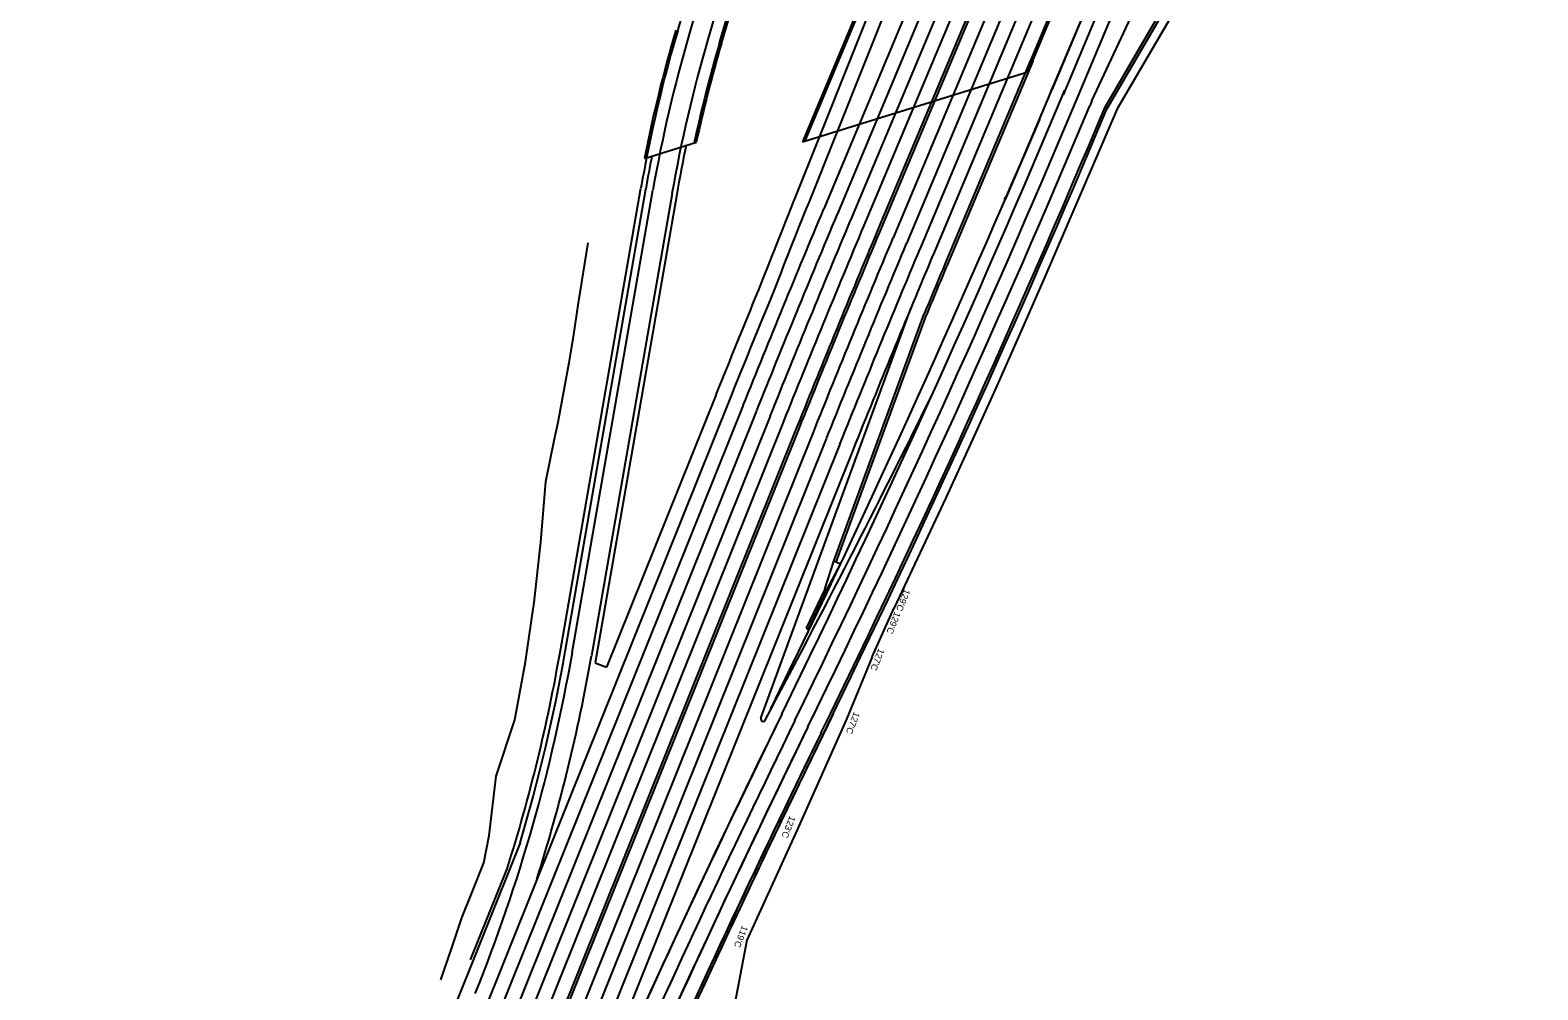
# Model space of a CAD drawing. Extents: x 1942118 to 1978871, y 789467 to 829913.
# Drawn here: x 1967729 to 1968973, y 795860 to 796652 of the extents above; entities that cross this region are included whole.
import ezdxf

# ---------------------------------------------------------------- set-up
doc = ezdxf.new("R2010")
doc.units = 0
for name, color, linetype in [('BR_CONCRETE', 7, 'Continuous'), ('RD_PD_ALT1_TrvlWay', 7, 'Continuous'), ('RD_PD_CstnLmt', 7, 'Continuous'), ('RD_PD_Final_LnLine', 7, 'Continuous'), ('RD_PD_Final_TrvlWay', 7, 'Continuous'), ('RD_PD_GR', 7, 'Continuous'), ('RD_PD_MedBWall', 7, 'Continuous'), ('RD_PD_PaveShd', 7, 'Continuous'), ('RD_PD_TX_CstnLmt', 7, 'Continuous'), ('RD_PD_WallFill', 7, 'Continuous'), ('RD_QTY_Conc4Structures', 7, 'Continuous')]:
    doc.layers.add(name, color=color, linetype=linetype)

msp = doc.modelspace()

# ---------------------------------------------------------------- linework, layer by layer
at = {"layer": 'BR_CONCRETE'}
for p, q in [((1968667.1, 797277.4), (1968366.4, 796560.2)), ((1968668.6, 797276.7), (1968368.4, 796560.9)), ((1968803.3, 797220.3), (1968550.4, 796617.4)), ((1968804.8, 797219.6), (1968552.4, 796618)), ((1968263.5, 796651.9), (1968353.7, 796958.7)), ((1968298.1, 796641.8), (1968388.3, 796948.5)), ((1968299.6, 796641.3), (1968389.8, 796948.1)), ((1968366.4, 796560.2), (1968552.4, 796618)), ((1968236.1, 796546.5), (1968278.9, 796559.8))]:
    msp.add_line(p, q, dxfattribs=at)
for radius, end in [(1177.6, 168.9156), (1176, 168.873), (1140, 167.8912), (1138.4, 167.8451)]:
    msp.add_arc((1969391.7, 796320.1), radius, 163.611, end, dxfattribs=at)
at = {"layer": 'RD_PD_ALT1_TrvlWay'}
for p, q in [((1968735, 797248.9), (1968417.2, 796491)), ((1968759, 797238.8), (1968441.2, 796480.9)), ((1968792.2, 797224.9), (1968474.4, 796467)), ((1968600.4, 797083.1), (1968371.6, 796510.1)), ((1968273.1, 796649.1), (1968363.3, 796955.9)), ((1968288.5, 796644.6), (1968378.7, 796951.3)), ((1968176.5, 796138.5), (1968243, 796520.2)), ((1968258.8, 796517.4), (1968192.3, 796135.8)), ((1968332.2, 796084.4), (1968455.8, 796422.5)), ((1968306.3, 796347.2), (1968147.2, 795951.2)), ((1968350.8, 796329.3), (1967751.3, 794836.6)), ((1968374.9, 796319.6), (1968148.1, 795754.9)), ((1968408.3, 796306.2), (1968052.1, 795419.3))]:
    msp.add_line(p, q, dxfattribs=at)
for centre, radius, start, end in [((1969391.7, 796320.1), 1166, 163.611, 170.119), ((1969391.7, 796320.1), 1150, 163.611, 170.119), ((1979068.7, 792236.5), 11519.2, 158.2228, 158.6386), ((1978996.5, 792053.9), 11472.2, 157.24601, 158.11901), ((1978996.5, 792053.9), 11446.2, 157.24601, 158.11901), ((1978996.5, 792053.9), 11410.2, 157.24601, 158.11901), ((1978996.5, 792053.9), 11520.2, 157.66169, 158.11901), ((1959776.5, 800641.6), 9697.6, 331.95974, 333.73393), ((1966797.3, 796378.8), 1400, 338.119, 350.119), ((1966797.3, 796378.8), 1416, 342.4266, 350.119), ((1977342.9, 791688), 10012, 153.93129, 158.11901), ((1968334.1, 796083.7), 2, 159.9191, 331.9597), ((1977342.9, 791688), 9988, 153.93129, 158.11901)]:
    msp.add_arc(centre, radius, start, end, dxfattribs=at)
at = {"layer": 'RD_PD_CstnLmt'}
for p, q in [((1968698.4, 796710.8), (1968626.3, 796587.3)), ((1968626.3, 796587.3), (1968565.8, 796446.9)), ((1968565.8, 796446.9), (1968545.8, 796401.6)), ((1968545.8, 796401.6), (1968525.7, 796356.4)), ((1968525.7, 796356.4), (1968505.3, 796311.4)), ((1968505.3, 796311.4), (1968484.7, 796266.3)), ((1968484.7, 796266.3), (1968442.2, 796175.6)), ((1968424.1, 796135.1), (1968442.2, 796175.6)), ((1968424.1, 796135.1), (1968402.9, 796083.7)), ((1968402.9, 796083.7), (1968362, 795992.3)), ((1968391.9, 796088.1), (1968378.5, 796060.8)), ((1968378.5, 796060.8), (1968348.1, 795997.9)), ((1968362, 795992.3), (1968320.6, 795901.2)), ((1968320.6, 795901.2), (1968301.6, 795801))]:
    msp.add_line(p, q, dxfattribs=at)
msp.add_lwpolyline([(1968068, 795868.4), (1968077.1, 795894.9), (1968085.2, 795919.7), (1968093.9, 795940.8), (1968103.5, 795965.1), (1968108, 795987.6), (1968113.7, 796036.6), (1968129.1, 796082.9), (1968137.8, 796130.8), (1968143.1, 796166.9), (1968144.9, 796179.9), (1968150.5, 796229.7), (1968154.7, 796279.7), (1968161.5, 796313.6), (1968164.8, 796328.7), (1968173.8, 796377.9), (1968177.4, 796399.3), (1968181.5, 796427.3), (1968189.5, 796476.7)], dxfattribs=at)
at = {"layer": 'RD_PD_Final_LnLine'}
for p, q in [((1968592.6, 796594.5), (1968973.4, 797502.5)), ((1968701.8, 797262.8), (1968384, 796504.9)), ((1968712.9, 797258.2), (1968395, 796500.3)), ((1968724, 797253.5), (1968406.1, 796495.6)), ((1968770.1, 797234.2), (1968452.2, 796476.3)), ((1968781.2, 797229.5), (1968463.3, 796471.7)), ((1968328.5, 796338.2), (1967729.1, 794845.6)), ((1968339.7, 796333.8), (1967740.2, 794841.1)), ((1968317.4, 796342.7), (1968114.5, 795837.5)), ((1968386.1, 796315.1), (1968159.3, 795750.4)), ((1968397.2, 796310.7), (1968170.4, 795746)), ((1968147.2, 795951.2), (1968094.4, 795819.6))]:
    msp.add_line(p, q, dxfattribs=at)
for centre, radius, start, end in [((1959629, 800353.9), 9720, 333.93129, 337.24601), ((1978996.5, 792053.9), 11508.2, 157.24601, 158.11901), ((1978996.5, 792053.9), 11496.2, 157.24601, 158.11901), ((1978996.5, 792053.9), 11484.2, 157.24601, 158.11901), ((1978996.5, 792053.9), 11434.2, 157.24601, 158.11901), ((1978996.5, 792053.9), 11422.2, 157.24601, 158.11901), ((1977342.9, 791688), 10000, 153.93129, 158.11901)]:
    msp.add_arc(centre, radius, start, end, dxfattribs=at)
at = {"layer": 'RD_PD_Final_TrvlWay'}
for p, q in [((1968958.4, 797497.8), (1968581.5, 796599.1)), ((1968605.4, 796594), (1968732.5, 796866)), ((1968605.4, 796594), (1968603.6, 796589.8))]:
    msp.add_line(p, q, dxfattribs=at)
for centre, radius, start, end in [((1959629, 800353.9), 9708, 333.93129, 337.27075), ((1959629, 800353.9), 9732, 333.93129, 337.24601), ((1977342.9, 791688), 10012, 153.93129, 156.82865), ((1977342.9, 791688), 9988, 153.93129, 156.82865)]:
    msp.add_arc(centre, radius, start, end, dxfattribs=at)
at = {"layer": 'RD_PD_GR'}
for p, q in [((1968572.3, 796603), (1968603.8, 796678.1)), ((1968562, 796578.7), (1968533.8, 796512.5)), ((1968166.7, 796140.2), (1968233.2, 796521.9)), ((1968532.9, 796512.9), (1968533.9, 796514.6)), ((1968533.8, 796512.5), (1968532.9, 796512.9)), ((1968534.6, 796514.3), (1968533.8, 796512.5)), ((1968533.9, 796514.6), (1968534.6, 796514.3)), ((1968384.9, 796191), (1968369.4, 796158.6)), ((1968386.7, 796190.2), (1968371.2, 796157.8)), ((1968369.4, 796158.6), (1968371.2, 796157.8)), ((1968092.6, 795885), (1968122.7, 795960))]:
    msp.add_line(p, q, dxfattribs=at)
for centre, radius, start, end in [((1959629, 800353.9), 9698, 337.09036, 337.27075), ((1969391.7, 796320.1), 1176, 168.873, 170.119), ((1966797.3, 796378.8), 1390, 342.4668, 350.119), ((1977342.9, 791688), 9976, 155.25302, 155.82448)]:
    msp.add_arc(centre, radius, start, end, dxfattribs=at)
at = {"layer": 'RD_PD_MedBWall'}
for p, q in [((1968746.1, 797244.2), (1968428.2, 796486.4)), ((1968748, 797243.5), (1968430.1, 796485.6)), ((1968554.7, 796627.5), (1968485.4, 796462.4)), ((1968556.5, 796626.7), (1968487.3, 796461.6)), ((1968394.2, 796213.2), (1968468.8, 796417.4)), ((1968361.9, 796324.8), (1968135.1, 795760.1)), ((1968363.8, 796324.1), (1968137, 795759.4))]:
    msp.add_line(p, q, dxfattribs=at)
for radius, end in [(11460.2, 158.11901), (11458.2, 158.11901), (11398.2, 157.48694), (11396.2, 157.48673)]:
    msp.add_arc((1978996.5, 792053.9), radius, 157.24601, end, dxfattribs=at)
at = {"layer": 'RD_PD_PaveShd'}
for p, q in [((1968945.9, 797493.9), (1968572.3, 796603)), ((1968589.3, 797087.5), (1968360.5, 796514.6)), ((1968170.6, 796139.5), (1968237.1, 796521.2)), ((1968262.7, 796516.7), (1968195.4, 796130.2)), ((1968392.3, 796213.9), (1968467, 796418.1)), ((1968295.1, 796351.7), (1968204.7, 796126.5)), ((1968397.8, 796211.6), (1968392.3, 796213.9)), ((1968195.4, 796130.2), (1968204.7, 796126.5)), ((1968133.5, 795981.4), (1968072.1, 795828.6))]:
    msp.add_line(p, q, dxfattribs=at)
for centre, radius, start, end in [((1959629, 800353.9), 9698, 333.93129, 337.27075), ((1959629, 800353.9), 9744, 333.93129, 337.26924), ((1969391.7, 796320.1), 1146, 168.0597, 170.119), ((1969391.7, 796320.1), 1172, 168.7673, 170.119), ((1979068.7, 792236.5), 11531.2, 158.2228, 158.6386), ((1978996.5, 792053.9), 11532.2, 157.66169, 158.11901), ((1966797.3, 796378.8), 1394, 343.4369, 350.119), ((1977342.9, 791688), 9976, 153.93129, 156.82865)]:
    msp.add_arc(centre, radius, start, end, dxfattribs=at)
at = {"layer": 'RD_PD_WallFill'}
for p, q in [((1968616.2, 796588.8), (1968671.8, 796684.1)), ((1968617.9, 796587.8), (1968673.6, 796683.2)), ((1968284.8, 795863.2), (1968283, 795864.1))]:
    msp.add_line(p, q, dxfattribs=at)
for centre, radius, start, end in [((1959629, 800353.9), 9744, 333.93129, 337.26924), ((1959629, 800353.9), 9746, 333.93129, 337.26874), ((1977342.9, 791688), 9976, 153.93129, 158.11901), ((1977342.9, 791688), 9974, 153.93129, 158.11901), ((1977342.9, 791688), 9976, 153.93129, 155.25302), ((1977342.9, 791688), 9974, 153.93129, 155.25302)]:
    msp.add_arc(centre, radius, start, end, dxfattribs=at)
at = {"layer": 'RD_QTY_Conc4Structures'}
for p, q in [((1968384.9, 796191), (1968392.3, 796213.9)), ((1968386.7, 796190.2), (1968397.8, 796211.6)), ((1968386.7, 796190.2), (1968384.9, 796191))]:
    msp.add_line(p, q, dxfattribs=at)

# ---------------------------------------------------------------- texts
at = {"layer": 'RD_PD_TX_CstnLmt'}
for s, p in [("129'C", (1968450.6, 796191.4)), ("129'C", (1968442.6, 796172.6)), ("127'C", (1968429.3, 796142.3)), ("127'C", (1968409.1, 796090)), ("123'C", (1968356, 796004.1)), ("119'C", (1968316.7, 795913.6))]:
    msp.add_text(s, height=5.4, rotation=248.119, dxfattribs=at).set_placement(p)

doc.saveas('drawing.dxf')
